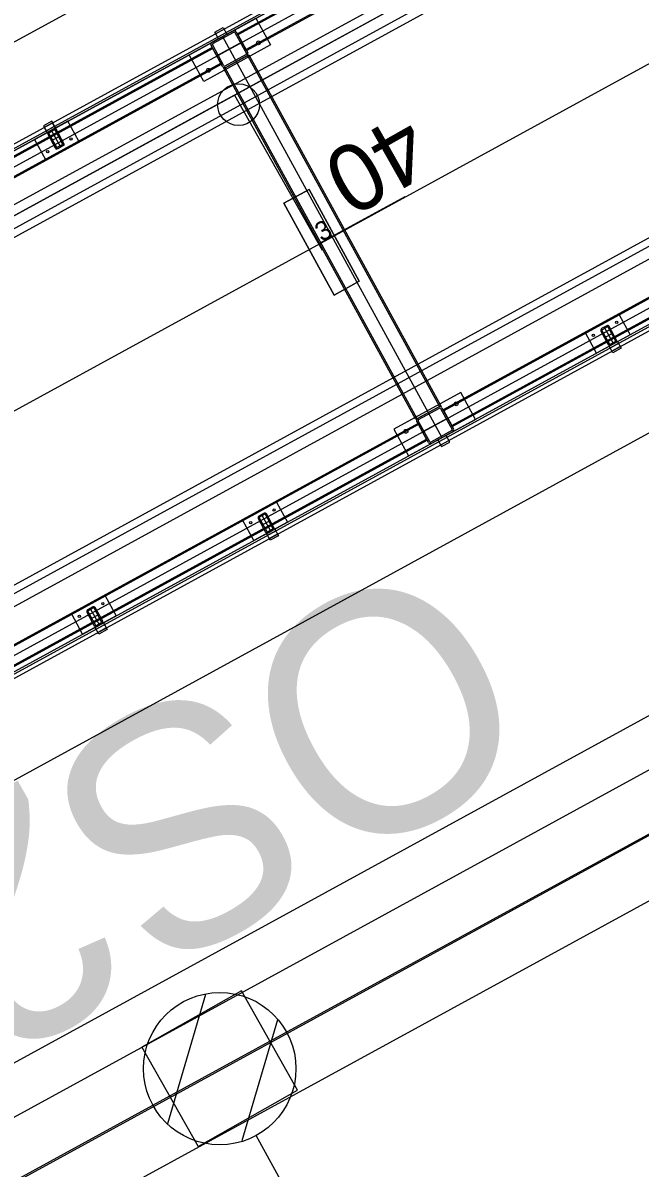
# Model space of a CAD drawing. Extents: x -783978 to -783565, y -1064821 to -1064596.
# Drawn here: x -783767.84 to -783764.6, y -1064687.65 to -1064681.64 of the extents above; entities that cross this region are included whole.
import ezdxf

# ---------------------------------------------------------------- set-up
doc = ezdxf.new("R2010")
doc.units = 0
for name, color, linetype in [('Default', 7, 'Continuous'), ('SO 01_20_01', 7, 'Continuous'), ('SO 01_50_01', 7, 'Continuous'), ('SO 01_74_01', 7, 'Continuous'), ('SO 01_79_02', 7, 'Continuous'), ('SO 01_86_02', 7, 'Continuous'), ('SO 01_86_03', 7, 'Continuous'), ('SO 01_86_04', 7, 'Continuous')]:
    doc.layers.add(name, color=color, linetype=linetype)

# ---------------------------------------------------------------- blocks, each defined once
blk = doc.blocks.new('POINT_DISPLAY')
at = {"layer": 'Default'}
blk.add_line((0, 0), (0, 0), dxfattribs=at)

msp = doc.modelspace()

# ---------------------------------------------------------------- linework, layer by layer
at = {"layer": 'SO 01_20_01'}
for p, q in [((-783735.0054, -1064663.7532), (-783787.4671, -1064692.4555)), ((-783735.2041, -1064664.4318), (-783786.7885, -1064692.6541)), ((-783786.6445, -1064692.9173), (-783735.3233, -1064664.839)), ((-783738.0171, -1064666.3812), (-783786.4402, -1064692.874)), ((-783786.421, -1064692.9091), (-783737.9979, -1064666.4163)), ((-783737.8741, -1064667.2605), (-783785.3352, -1064693.2269)), ((-783737.0912, -1064667.858), (-783785.7805, -1064694.4964)), ((-783785.6531, -1064694.3127), (-783737.23, -1064667.82)), ((-783737.2108, -1064667.855), (-783785.6339, -1064694.3478)), ((-783785.6366, -1064694.7596), (-783736.9472, -1064668.1212)), ((-783746.2961, -1064673.8055), (-783785.8354, -1064695.4379))]:
    msp.add_line(p, q, dxfattribs=at)
at = {"layer": 'SO 01_50_01'}
for p, q in [((-783786.7885, -1064692.6541), (-783725.4827, -1064659.1131)), ((-783769.2428, -1064683.0547), (-783764.8564, -1064680.6549)), ((-783769.2427, -1064683.0548), (-783764.8563, -1064680.655)), ((-783769.2427, -1064683.0548), (-783764.8563, -1064680.655))]:
    msp.add_line(p, q, dxfattribs=at)
for points in [[(-783784.7751, -1064696.3401), (-783745.2333, -1064674.7064)], [(-783784.6553, -1064696.5595), (-783745.1133, -1064674.9257)]]:
    msp.add_lwpolyline(points, dxfattribs=at)
at = {"layer": 'SO 01_74_01'}
for p, q in [((-783735.2185, -1064664.4055), (-783786.6099, -1064692.5222)), ((-783786.6003, -1064692.5398), (-783735.2089, -1064664.423)), ((-783785.4388, -1064694.6628), (-783745.8293, -1064672.9921)), ((-783745.8197, -1064673.0096), (-783785.4292, -1064694.6803)), ((-783764.1469, -1064680.2952), (-783766.713, -1064681.6991)), ((-783764.1439, -1064680.3007), (-783766.71, -1064681.7047)), ((-783766.668, -1064681.7813), (-783764.102, -1064680.3774)), ((-783766.665, -1064681.7869), (-783764.0989, -1064680.383)), ((-783766.8319, -1064681.6901), (-783766.7881, -1064681.6661)), ((-783766.8127, -1064681.7252), (-783766.8319, -1064681.6901)), ((-783766.7881, -1064681.6661), (-783766.7689, -1064681.7012)), ((-783766.7689, -1064681.7012), (-783766.8127, -1064681.7252)), ((-783766.713, -1064681.6991), (-783766.665, -1064681.7869)), ((-783766.71, -1064681.7047), (-783766.668, -1064681.7813)), ((-783766.8446, -1064681.7711), (-783769.4106, -1064683.175)), ((-783766.8416, -1064681.7767), (-783769.4076, -1064683.1806)), ((-783766.7966, -1064681.8589), (-783766.8446, -1064681.7711)), ((-783766.7996, -1064681.8533), (-783766.8416, -1064681.7767)), ((-783766.7846, -1064681.8808), (-783766.653, -1064681.8088)), ((-783766.653, -1064681.8088), (-783765.6451, -1064683.6511)), ((-783769.3657, -1064683.2572), (-783766.7996, -1064681.8533)), ((-783769.3626, -1064683.2628), (-783766.7966, -1064681.8589)), ((-783766.7776, -1064681.877), (-783766.66, -1064681.8126)), ((-783766.66, -1064681.8126), (-783765.6521, -1064683.6549)), ((-783765.7766, -1064683.7231), (-783766.7846, -1064681.8808)), ((-783765.7696, -1064683.7193), (-783766.7776, -1064681.877)), ((-783767.6873, -1064682.1581), (-783767.7311, -1064682.1821)), ((-783767.6825, -1064682.1669), (-783767.7263, -1064682.1909)), ((-783767.6681, -1064682.1932), (-783767.6873, -1064682.1581)), ((-783767.6729, -1064682.1844), (-783767.6825, -1064682.1669)), ((-783767.7311, -1064682.1821), (-783767.7119, -1064682.2172)), ((-783767.7263, -1064682.1909), (-783767.7167, -1064682.2084)), ((-783767.7167, -1064682.2084), (-783767.6729, -1064682.1844)), ((-783767.7119, -1064682.2172), (-783767.6681, -1064682.1932)), ((-783763.067, -1064682.2691), (-783765.6331, -1064683.673)), ((-783763.064, -1064682.2746), (-783765.63, -1064683.6786)), ((-783765.5881, -1064683.7552), (-783763.022, -1064682.3513)), ((-783765.5851, -1064683.7608), (-783763.019, -1064682.3568)), ((-783764.7616, -1064683.3387), (-783764.7177, -1064683.3147)), ((-783764.7177, -1064683.3147), (-783764.6985, -1064683.3498)), ((-783764.7424, -1064683.3738), (-783764.7616, -1064683.3387)), ((-783764.7568, -1064683.3475), (-783764.7129, -1064683.3235)), ((-783764.7472, -1064683.365), (-783764.7568, -1064683.3475)), ((-783764.7033, -1064683.341), (-783764.7472, -1064683.365)), ((-783764.6985, -1064683.3498), (-783764.7424, -1064683.3738)), ((-783764.7129, -1064683.3235), (-783764.7033, -1064683.341)), ((-783765.6451, -1064683.6511), (-783765.7766, -1064683.7231)), ((-783765.6521, -1064683.6549), (-783765.7696, -1064683.7193)), ((-783765.6331, -1064683.673), (-783765.5851, -1064683.7608)), ((-783765.63, -1064683.6786), (-783765.5881, -1064683.7552)), ((-783765.7646, -1064683.745), (-783768.3307, -1064685.1489)), ((-783765.7616, -1064683.7505), (-783768.3277, -1064685.1545)), ((-783765.7167, -1064683.8328), (-783765.7646, -1064683.745)), ((-783765.7197, -1064683.8272), (-783765.7616, -1064683.7505)), ((-783768.2857, -1064685.2311), (-783765.7197, -1064683.8272)), ((-783768.2827, -1064685.2367), (-783765.7167, -1064683.8328)), ((-783765.6169, -1064683.8067), (-783765.6608, -1064683.8307)), ((-783765.6608, -1064683.8307), (-783765.6416, -1064683.8658)), ((-783765.6416, -1064683.8658), (-783765.5977, -1064683.8418)), ((-783765.5977, -1064683.8418), (-783765.6169, -1064683.8067)), ((-783766.56, -1064684.3227), (-783766.5161, -1064684.2987)), ((-783766.5408, -1064684.3577), (-783766.56, -1064684.3227)), ((-783766.5552, -1064684.3314), (-783766.5113, -1064684.3074)), ((-783766.5456, -1064684.349), (-783766.5552, -1064684.3314)), ((-783766.5017, -1064684.325), (-783766.5456, -1064684.349)), ((-783766.4969, -1064684.3337), (-783766.5408, -1064684.3577)), ((-783766.5161, -1064684.2987), (-783766.4969, -1064684.3337)), ((-783766.5113, -1064684.3074), (-783766.5017, -1064684.325)), ((-783767.4592, -1064684.8146), (-783767.4154, -1064684.7906)), ((-783767.44, -1064684.8497), (-783767.4592, -1064684.8146)), ((-783767.4544, -1064684.8234), (-783767.4106, -1064684.7994)), ((-783767.401, -1064684.8169), (-783767.4448, -1064684.8409)), ((-783767.4154, -1064684.7906), (-783767.3962, -1064684.8257)), ((-783767.4106, -1064684.7994), (-783767.401, -1064684.8169)), ((-783767.4448, -1064684.8409), (-783767.4544, -1064684.8234)), ((-783767.3962, -1064684.8257), (-783767.44, -1064684.8497))]:
    msp.add_line(p, q, dxfattribs=at)
for points in [[(-783735.1681, -1064664.4976), (-783787.4762, -1064693.1159)], [(-783734.0882, -1064666.4715), (-783786.3963, -1064695.0898)], [(-783766.8461, -1064681.7434), (-783766.7355, -1064681.683)], [(-783766.8422, -1064681.7505), (-783766.7317, -1064681.69)], [(-783766.7262, -1064681.6916), (-783766.6658, -1064681.8021)], [(-783766.7192, -1064681.6877), (-783766.6588, -1064681.7983)], [(-783766.689, -1064681.743), (-783766.8206, -1064681.815)], [(-783766.7908, -1064681.7132), (-783765.6389, -1064683.8187)], [(-783766.7908, -1064681.7132), (-783766.7188, -1064681.8448)], [(-783766.7903, -1064681.8703), (-783766.8508, -1064681.7597)], [(-783766.7833, -1064681.8664), (-783766.8438, -1064681.7559)], [(-783766.6674, -1064681.8075), (-783766.7779, -1064681.868)], [(-783766.6635, -1064681.8146), (-783766.7741, -1064681.875)], [(-783767.7074, -1064682.2255), (-783767.6685, -1064682.2966)], [(-783767.6764, -1064682.1977), (-783767.7036, -1064682.2126)], [(-783767.7019, -1064682.2224), (-783767.6629, -1064682.2936)], [(-783767.6733, -1064682.2032), (-783767.7006, -1064682.2182)], [(-783767.69, -1064682.2052), (-783767.642, -1064682.2929)], [(-783767.6301, -1064682.2756), (-783767.6691, -1064682.2045)], [(-783767.6246, -1064682.2726), (-783767.6635, -1064682.2015)], [(-783767.6441, -1064682.237), (-783767.6879, -1064682.261)], [(-783767.6587, -1064682.2948), (-783767.6314, -1064682.2799)], [(-783767.6556, -1064682.3004), (-783767.6284, -1064682.2854)], [(-783764.774, -1064683.2315), (-783764.8013, -1064683.2465)], [(-783764.771, -1064683.2371), (-783764.7983, -1064683.252)], [(-783764.7876, -1064683.239), (-783764.7396, -1064683.3267)], [(-783764.7278, -1064683.3094), (-783764.7667, -1064683.2383)], [(-783764.7222, -1064683.3064), (-783764.7612, -1064683.2353)], [(-783764.805, -1064683.2593), (-783764.7661, -1064683.3304)], [(-783764.7995, -1064683.2563), (-783764.7606, -1064683.3274)], [(-783764.7417, -1064683.2709), (-783764.7856, -1064683.2949)], [(-783764.7563, -1064683.3287), (-783764.729, -1064683.3137)], [(-783764.7533, -1064683.3342), (-783764.726, -1064683.3193)], [(-783765.7661, -1064683.7173), (-783765.6556, -1064683.6569)], [(-783765.7623, -1064683.7243), (-783765.6517, -1064683.6639)], [(-783765.6463, -1064683.6655), (-783765.5858, -1064683.776)], [(-783765.6393, -1064683.6616), (-783765.5788, -1064683.7722)], [(-783765.7104, -1064683.8442), (-783765.7709, -1064683.7336)], [(-783765.7034, -1064683.8403), (-783765.7639, -1064683.7298)], [(-783765.6091, -1064683.7169), (-783765.7407, -1064683.7889)], [(-783765.7109, -1064683.6871), (-783765.6389, -1064683.8187)], [(-783765.5874, -1064683.7814), (-783765.698, -1064683.8419)], [(-783765.5836, -1064683.7884), (-783765.6941, -1064683.8489)], [(-783766.5724, -1064684.2155), (-783766.5997, -1064684.2304)], [(-783766.6035, -1064684.2432), (-783766.5645, -1064684.3144)], [(-783766.5979, -1064684.2402), (-783766.559, -1064684.3113)], [(-783766.5694, -1064684.221), (-783766.5967, -1064684.2359)], [(-783766.5861, -1064684.2229), (-783766.5381, -1064684.3107)], [(-783766.5401, -1064684.2548), (-783766.584, -1064684.2788)], [(-783766.5262, -1064684.2934), (-783766.5651, -1064684.2222)], [(-783766.5207, -1064684.2904), (-783766.5596, -1064684.2192)], [(-783766.5547, -1064684.3126), (-783766.5275, -1064684.2977)], [(-783766.5517, -1064684.3181), (-783766.5244, -1064684.3032)], [(-783767.5027, -1064684.7352), (-783767.4638, -1064684.8063)], [(-783767.4716, -1064684.7074), (-783767.4989, -1064684.7224)], [(-783767.4972, -1064684.7322), (-783767.4582, -1064684.8033)], [(-783767.4686, -1064684.713), (-783767.4959, -1064684.7279)], [(-783767.4853, -1064684.7149), (-783767.4373, -1064684.8026)], [(-783767.4394, -1064684.7468), (-783767.4832, -1064684.7708)], [(-783767.4254, -1064684.7854), (-783767.4643, -1064684.7142)], [(-783767.4199, -1064684.7823), (-783767.4588, -1064684.7112)], [(-783767.454, -1064684.8046), (-783767.4267, -1064684.7896)], [(-783767.4509, -1064684.8101), (-783767.4236, -1064684.7952)]]:
    msp.add_lwpolyline(points, dxfattribs=at)
for points in [[(-783766.5385, -1064681.7576), (-783766.8894, -1064681.9496), (-783766.9662, -1064681.8092), (-783766.6153, -1064681.6172)], [(-783767.6023, -1064682.1572), (-783767.7777, -1064682.2532), (-783767.7201, -1064682.3584), (-783767.5447, -1064682.2625)], [(-783767.6681, -1064682.1932), (-783767.7119, -1064682.2172), (-783767.6639, -1064682.3049), (-783767.6201, -1064682.2809)], [(-783764.6519, -1064683.2787), (-783764.8274, -1064683.3747), (-783764.885, -1064683.2694), (-783764.7095, -1064683.1734)], [(-783765.5402, -1064683.5823), (-783765.8911, -1064683.7743), (-783765.8143, -1064683.9147), (-783765.4634, -1064683.7227)], [(-783766.4503, -1064684.2627), (-783766.6258, -1064684.3587), (-783766.6834, -1064684.2534), (-783766.5079, -1064684.1574)], [(-783767.3496, -1064684.7546), (-783767.525, -1064684.8506), (-783767.5826, -1064684.7453), (-783767.4072, -1064684.6494)]]:
    msp.add_lwpolyline(points, close=True, dxfattribs=at)
for centre, radius in [((-783766.6016, -1064681.7465), 0.01), ((-783766.8648, -1064681.8905), 0.01), ((-783767.5854, -1064682.2505), 0.006), ((-783767.7082, -1064682.3177), 0.006), ((-783764.7214, -1064683.2142), 0.006), ((-783764.8442, -1064683.2814), 0.006), ((-783765.5649, -1064683.6414), 0.01), ((-783765.828, -1064683.7854), 0.01), ((-783766.5199, -1064684.1981), 0.006), ((-783766.6427, -1064684.2653), 0.006), ((-783767.4191, -1064684.6901), 0.006), ((-783767.5419, -1064684.7573), 0.006)]:
    msp.add_circle(centre, radius, dxfattribs=at)
for centre, radius, start, end in [((-783766.7298, -1064681.6935), 0.012, 28.68349, 118.68349), ((-783766.7298, -1064681.6935), 0.004, 28.68349, 118.68349), ((-783766.8403, -1064681.754), 0.012, 118.68349, 208.68349), ((-783766.8403, -1064681.754), 0.004, 118.68349, 208.68349), ((-783766.6693, -1064681.804), 0.004, 298.68349, 28.68349), ((-783766.6693, -1064681.804), 0.012, 298.68349, 28.68349), ((-783766.7798, -1064681.8645), 0.012, 208.68349, 298.68349), ((-783766.7798, -1064681.8645), 0.004, 208.68349, 298.68349), ((-783767.6991, -1064682.2209), 0.00945, 118.68349, 208.68349), ((-783767.6991, -1064682.2209), 0.00315, 118.68349, 208.68349), ((-783767.6718, -1064682.206), 0.00945, 28.68349, 118.68349), ((-783767.6718, -1064682.206), 0.00315, 28.68349, 118.68349), ((-783767.6329, -1064682.2771), 0.00315, 298.68349, 28.68349), ((-783767.6329, -1064682.2771), 0.00945, 298.68349, 28.68349), ((-783767.6602, -1064682.2921), 0.00945, 208.68349, 298.68349), ((-783767.6602, -1064682.2921), 0.00315, 208.68349, 298.68349), ((-783764.7967, -1064683.2547), 0.00945, 118.68349, 208.68349), ((-783764.7967, -1064683.2547), 0.00315, 118.68349, 208.68349), ((-783764.7695, -1064683.2398), 0.00945, 28.68349, 118.68349), ((-783764.7695, -1064683.2398), 0.00315, 28.68349, 118.68349), ((-783764.7305, -1064683.311), 0.00315, 298.68349, 28.68349), ((-783764.7305, -1064683.311), 0.00945, 298.68349, 28.68349), ((-783764.7578, -1064683.3259), 0.00945, 208.68349, 298.68349), ((-783764.7578, -1064683.3259), 0.00315, 208.68349, 298.68349), ((-783765.6498, -1064683.6674), 0.012, 28.68349, 118.68349), ((-783765.6498, -1064683.6674), 0.004, 28.68349, 118.68349), ((-783765.7604, -1064683.7279), 0.012, 118.68349, 208.68349), ((-783765.7604, -1064683.7279), 0.004, 118.68349, 208.68349), ((-783765.5893, -1064683.7779), 0.004, 298.68349, 28.68349), ((-783765.5893, -1064683.7779), 0.012, 298.68349, 28.68349), ((-783765.6999, -1064683.8384), 0.012, 208.68349, 298.68349), ((-783765.6999, -1064683.8384), 0.004, 208.68349, 298.68349), ((-783766.5679, -1064684.2238), 0.00945, 28.68349, 118.68349), ((-783766.5952, -1064684.2387), 0.00945, 118.68349, 208.68349), ((-783766.5952, -1064684.2387), 0.00315, 118.68349, 208.68349), ((-783766.5679, -1064684.2238), 0.00315, 28.68349, 118.68349), ((-783766.5563, -1064684.3098), 0.00945, 208.68349, 298.68349), ((-783766.5563, -1064684.3098), 0.00315, 208.68349, 298.68349), ((-783766.529, -1064684.2949), 0.00315, 298.68349, 28.68349), ((-783766.529, -1064684.2949), 0.00945, 298.68349, 28.68349), ((-783767.4944, -1064684.7307), 0.00945, 118.68349, 208.68349), ((-783767.4944, -1064684.7307), 0.00315, 118.68349, 208.68349), ((-783767.4671, -1064684.7157), 0.00945, 28.68349, 118.68349), ((-783767.4671, -1064684.7157), 0.00315, 28.68349, 118.68349), ((-783767.4555, -1064684.8018), 0.00945, 208.68349, 298.68349), ((-783767.4555, -1064684.8018), 0.00315, 208.68349, 298.68349), ((-783767.4282, -1064684.7869), 0.00315, 298.68349, 28.68349), ((-783767.4282, -1064684.7869), 0.00945, 298.68349, 28.68349)]:
    msp.add_arc(centre, radius, start, end, dxfattribs=at)
at = {"layer": 'SO 01_79_02'}
msp.add_lwpolyline([(-783745.0819, -1064674.9774), (-783746.507, -1064675.7571), (-783748.1468, -1064676.6636), (-783749.6912, -1064678.1356), (-783784.2571, -1064697.0125), (-783798.19, -1064704.62), (-783800.06, -1064705.37), (-783802.52, -1064706.72), (-783803.71, -1064707.63), (-783853.11, -1064734.61), (-783855.1, -1064735.3), (-783857.05, -1064736.37), (-783858.65, -1064737.64), (-783871.68, -1064744.75), (-783877.0563, -1064744.607), (-783887.4289, -1064744.0617), (-783898.0887, -1064743.4896), (-783899.4205, -1064743.4179)], dxfattribs=at)
at = {"layer": 'SO 01_86_02'}
for p, q in [((-783766.8804, -1064686.7424), (-783767.0791, -1064687.421)), ((-783766.5028, -1064686.8743), (-783766.6891, -1064687.5109)), ((-783765.8937, -1064688.7981), (-783766.6136, -1064687.4821))]:
    msp.add_line(p, q, dxfattribs=at)
msp.add_lwpolyline([(-783878.1861, -1064744.2753), (-783875.1286, -1064744.3451), (-783874.6948, -1064744.3279), (-783873.2511, -1064744.1567), (-783872.3143, -1064743.9824), (-783871.2185, -1064743.7022), (-783870.5149, -1064743.4863), (-783869.7975, -1064743.2125), (-783869.1775, -1064742.9745), (-783868.7111, -1064742.7654), (-783868.3945, -1064742.6073), (-783868.078, -1064742.4492), (-783860.9748, -1064738.5687), (-783850.6715, -1064732.6113), (-783846.2461, -1064730.1894), (-783839.9469, -1064727.0857), (-783822.4265, -1064717.4271), (-783813.3562, -1064712.518), (-783804.2851, -1064707.6104), (-783794.4737, -1064702.2521), (-783784.6611, -1064696.8962), (-783775.7336, -1064692.0133), (-783766.8056, -1064687.1312), (-783750.6261, -1064678.2817)], dxfattribs=at)
msp.add_lwpolyline([(-783766.9193, -1064687.54), (-783766.3969, -1064687.2449), (-783766.692, -1064686.7225), (-783767.2144, -1064687.0176)], close=True, dxfattribs=at)
msp.add_circle((-783766.8056, -1064687.1312), 0.4, dxfattribs=at)
at = {"layer": 'SO 01_86_03'}
msp.add_lwpolyline([(-783747.0305, -1064676.621), (-783747.6236, -1064677.108), (-783750.7299, -1064678.7824), (-783751.6662, -1064678.8522), (-783782.6812, -1064695.8307), (-783782.8877, -1064696.6917), (-783783.0615, -1064696.8198), (-783783.3595, -1064696.8031), (-783786.8168, -1064690.1799), (-783787.333, -1064689.2371), (-783735.2095, -1064660.6967), (-783724.8208, -1064663.0486), (-783722.5212, -1064661.7932)], dxfattribs=at)
at = {"layer": 'SO 01_86_04'}
for p, q in [((-783766.7272, -1064682.0204), (-783766.267, -1064682.835)), ((-783766.3368, -1064682.5155), (-783766.4684, -1064682.5875)), ((-783766.3368, -1064682.5155), (-783766.4684, -1064682.5875)), ((-783766.4684, -1064682.5875), (-783766.3368, -1064682.5155)), ((-783766.4684, -1064682.5875), (-783766.3368, -1064682.5155)), ((-783766.0729, -1064682.998), (-783766.3368, -1064682.5155)), ((-783766.0729, -1064682.998), (-783766.3368, -1064682.5155)), ((-783766.3368, -1064682.5155), (-783766.0729, -1064682.998)), ((-783766.3368, -1064682.5155), (-783766.0729, -1064682.998)), ((-783766.4684, -1064682.5875), (-783766.2045, -1064683.07)), ((-783766.4684, -1064682.5875), (-783766.2045, -1064683.07)), ((-783766.2045, -1064683.07), (-783766.4684, -1064682.5875)), ((-783766.2045, -1064683.07), (-783766.4684, -1064682.5875)), ((-783766.2707, -1064682.7928), (-783765.832, -1064682.5528)), ((-783766.2045, -1064683.07), (-783766.0729, -1064682.998)), ((-783766.2045, -1064683.07), (-783766.0729, -1064682.998)), ((-783766.0729, -1064682.998), (-783766.2045, -1064683.07)), ((-783766.0729, -1064682.998), (-783766.2045, -1064683.07))]:
    msp.add_line(p, q, dxfattribs=at)
for points in [[(-783738.3222, -1064666.4797), (-783740.5325, -1064667.689), (-783743.1715, -1064669.1328), (-783745.7538, -1064670.5456), (-783748.4385, -1064672.0145), (-783751.0413, -1064673.4385), (-783753.6847, -1064674.8847), (-783756.3281, -1064676.3309), (-783758.9715, -1064677.7772), (-783761.6149, -1064679.2234), (-783764.2583, -1064680.6696), (-783766.9018, -1064682.1159), (-783769.4633, -1064683.5173), (-783772.109, -1064684.9648), (-783774.7882, -1064686.4306), (-783778.1382, -1064688.2722), (-783783.8139, -1064691.3971), (-783785.747, -1064692.4898)], [(-783747.063, -1064670.9765), (-783746.9575, -1064671.1681), (-783786.6893, -1064692.8619), (-783786.185, -1064693.7636)]]:
    msp.add_lwpolyline(points, dxfattribs=at)
msp.add_circle((-783766.7068, -1064682.0705), 0.1097, dxfattribs=at)

# ---------------------------------------------------------------- block references
at = {"layer": 'SO 01_86_04', "xscale": 0.010000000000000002, "yscale": 0.009999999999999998, "rotation": 28.683491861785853}
for p in [(-783766.3368, -1064682.5155), (-783766.3368, -1064682.5155), (-783766.4684, -1064682.5875), (-783766.4684, -1064682.5875), (-783766.0729, -1064682.998), (-783766.0729, -1064682.998), (-783766.2045, -1064683.07), (-783766.2045, -1064683.07)]:
    msp.add_blockref('POINT_DISPLAY', p, dxfattribs=at)

# ---------------------------------------------------------------- texts
at = {"layer": 'SO 01_86_02'}
msp.add_text('OS2', height=1.25, rotation=209.44605, dxfattribs=at).set_placement((-783765.6897, -1064684.3906))
at = {"layer": 'SO 01_86_04'}
for s, height, rotation, p in [('40', 0.351, 209.46001, (-783765.8339, -1064682.1046)), ('3', 0.1, 28.68349, (-783766.2707, -1064682.7928))]:
    msp.add_text(s, height=height, rotation=rotation, dxfattribs=at).set_placement(p)

doc.saveas('drawing.dxf')
